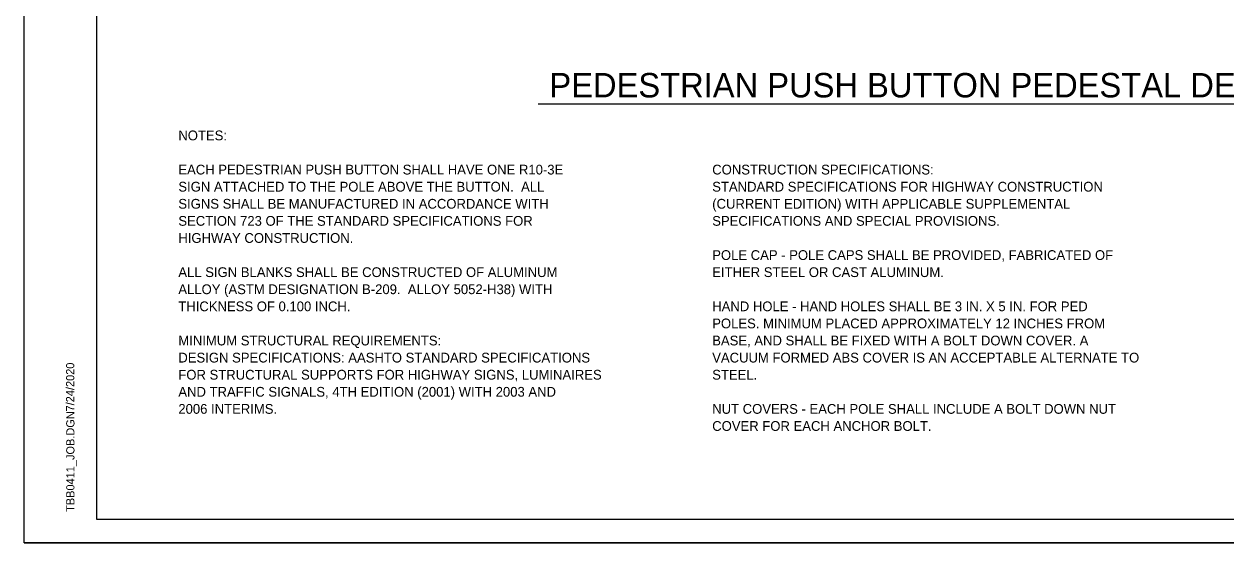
# Model space of a CAD drawing. Extents: x 1370140 to 1371141, y 380020 to 380660.
# Drawn here: x 1370140 to 1370755, y 380020 to 380286 of the extents above; entities that cross this region are included whole.
import ezdxf

# ---------------------------------------------------------------- set-up
doc = ezdxf.new("R2010")
doc.units = 0
for name, color, linetype in [('R_Border', 7, 'Continuous'), ('R_Draft', 7, 'Continuous'), ('R_No Plot', 7, 'Continuous')]:
    doc.layers.add(name, color=color, linetype=linetype)

msp = doc.modelspace()

# ---------------------------------------------------------------- linework, layer by layer
at = {"layer": 'R_Border'}
for p, q in [((1370177.71, 380031.98), (1370177.71, 380648.36)), ((1370177.71, 380031.98), (1370177.71, 380031.98)), ((1371126.25, 380031.98), (1370177.71, 380031.98))]:
    msp.add_line(p, q, dxfattribs=at)
at = {"layer": 'R_Draft'}
msp.add_line((1370403.46, 380244.78), (1370837.94, 380244.78), dxfattribs=at)
at = {"layer": 'R_No Plot'}
msp.add_line((1370140.51, 380020.04), (1371140.51, 380020.04), dxfattribs=at)
msp.add_lwpolyline([(1370140.49, 380660.04), (1371140.51, 380660.04), (1371140.51, 380020.03), (1370140.49, 380020.03)], close=True, dxfattribs=at)

# ---------------------------------------------------------------- texts
at = {"layer": 'R_Border'}
for s, p in [('7/24/2020', (1370166.19, 380087.37)), ('TBB0411_JOB.DGN', (1370166.28, 380035.95))]:
    msp.add_text(s, height=4.2, rotation=90, dxfattribs=at).set_placement(p)
at = {"layer": 'R_Draft'}
for s, height, p in [('PEDESTRIAN PUSH BUTTON PEDESTAL DETAIL', 12.5, (1370409.25, 380248.12)), ('NOTES:', 5, (1370219.43, 380226.16)), ('EACH PEDESTRIAN PUSH BUTTON SHALL HAVE ONE R10-3E ', 5, (1370219.43, 380208.66)), ('CONSTRUCTION SPECIFICATIONS:', 5, (1370492.55, 380208.66)), ('SIGN ATTACHED TO THE POLE ABOVE THE BUTTON.  ALL ', 5, (1370219.43, 380199.91)), ('STANDARD SPECIFICATIONS FOR HIGHWAY CONSTRUCTION ', 5, (1370492.55, 380199.91)), ('SIGNS SHALL BE MANUFACTURED IN ACCORDANCE WITH ', 5, (1370219.43, 380191.16)), ('(CURRENT EDITION) WITH APPLICABLE SUPPLEMENTAL ', 5, (1370492.55, 380191.16)), ('SECTION 723 OF THE STANDARD SPECIFICATIONS FOR ', 5, (1370219.43, 380182.41)), ('SPECIFICATIONS AND SPECIAL PROVISIONS.', 5, (1370492.55, 380182.41)), ('HIGHWAY CONSTRUCTION.', 5, (1370219.43, 380173.66)), ('POLE CAP - POLE CAPS SHALL BE PROVIDED, FABRICATED OF ', 5, (1370492.55, 380164.91)), ('ALL SIGN BLANKS SHALL BE CONSTRUCTED OF ALUMINUM ', 5, (1370219.43, 380156.16)), ('EITHER STEEL OR CAST ALUMINUM.', 5, (1370492.55, 380156.16)), ('ALLOY (ASTM DESIGNATION B-209.  ALLOY 5052-H38) WITH ', 5, (1370219.43, 380147.41)), ('THICKNESS OF 0.100 INCH.', 5, (1370219.43, 380138.66)), ('HAND HOLE - HAND HOLES SHALL BE 3 IN. X 5 IN. FOR PED ', 5, (1370492.55, 380138.66)), ('POLES. MINIMUM PLACED APPROXIMATELY 12 INCHES FROM ', 5, (1370492.55, 380129.91)), ('MINIMUM STRUCTURAL REQUIREMENTS:', 5, (1370219.43, 380121.16)), ('BASE, AND SHALL BE FIXED WITH A BOLT DOWN COVER. A ', 5, (1370492.55, 380121.16)), ('DESIGN SPECIFICATIONS: AASHTO STANDARD SPECIFICATIONS ', 5, (1370219.43, 380112.41)), ('VACUUM FORMED ABS COVER IS AN ACCEPTABLE ALTERNATE TO ', 5, (1370492.55, 380112.41)), ('FOR STRUCTURAL SUPPORTS FOR HIGHWAY SIGNS, LUMINAIRES ', 5, (1370219.43, 380103.66)), ('STEEL. ', 5, (1370492.55, 380103.66)), ('AND TRAFFIC SIGNALS, 4TH EDITION (2001) WITH 2003 AND ', 5, (1370219.43, 380094.91)), ('2006 INTERIMS.', 5, (1370219.43, 380086.16)), ('NUT COVERS - EACH POLE SHALL INCLUDE A BOLT DOWN NUT ', 5, (1370492.55, 380086.16)), ('COVER FOR EACH ANCHOR BOLT.', 5, (1370492.55, 380077.41))]:
    msp.add_text(s, height=height, dxfattribs=at).set_placement(p)

doc.saveas('drawing.dxf')
